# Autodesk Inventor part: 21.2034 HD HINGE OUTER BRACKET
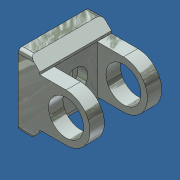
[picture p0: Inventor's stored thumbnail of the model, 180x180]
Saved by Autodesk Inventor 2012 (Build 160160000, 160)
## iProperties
Created: 2014-05
Part Number: 21.2034 HD HINGE OUTER BRACKET
Material: Steel
Document SubType Name: Modeling
Designer: Admin
Density: 7.85 g/cm^3
Mass: 251.325 g
Surface Area: 111.749 cm^2
Volume: 32.0159 cm^3
Author: Admin
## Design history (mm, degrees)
node "Product1"
node "Base1"
body "Solid1"
